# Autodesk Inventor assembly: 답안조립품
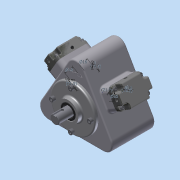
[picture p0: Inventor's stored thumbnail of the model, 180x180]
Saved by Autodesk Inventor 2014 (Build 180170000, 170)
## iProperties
Created: 2015-06
Part Number: 답안조립품
Document SubType Name: Assembly
Designer: MYHOME
Author: MYHOME
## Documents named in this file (20)
- C:\Documents and Settings\MYHOME\바탕 화면\350605V1037\답안조립품.iam
- C:\Documents and Settings\MYHOME\바탕 화면\350605V1037\본체.ipt
- C:\Documents and Settings\MYHOME\바탕 화면\350605V1037\헤더커버.ipt
- 헤더커버.ipt
- C:\Documents and Settings\MYHOME\바탕 화면\350605V1037\부시.ipt
- C:\Documents and Settings\MYHOME\바탕 화면\350605V1037\베어링 NA 4904.ipt
- 베어링 NA 4904.ipt
- C:\Documents and Settings\MYHOME\바탕 화면\350605V1037\편심축.ipt
- C:\Documents and Settings\MYHOME\바탕 화면\350605V1037\앞커버.ipt
- C:\Documents and Settings\MYHOME\바탕 화면\350605V1037\오일실.ipt
- 오일실.ipt
- C:\Documents and Settings\MYHOME\바탕 화면\350605V1037\M6x0.7x20.ipt
- M6x0.7x20.ipt
- C:\Documents and Settings\MYHOME\바탕 화면\350605V1037\슬라이드.ipt
- C:\Documents and Settings\MYHOME\바탕 화면\350605V1037\M4x0.5x16.ipt
- M4x0.5x16.ipt
- C:\Documents and Settings\MYHOME\바탕 화면\350605V1037\8-스프링.ipt
- C:\Documents and Settings\MYHOME\바탕 화면\350605V1037\9-스프링.ipt
- C:\Documents and Settings\MYHOME\바탕 화면\350605V1037\10-스프링.ipt
- C:\Documents and Settings\MYHOME\바탕 화면\350605V1037\11-스프링.ipt
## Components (18 placed, 7 different names)
1. 헤더커버:1
2. 헤더커버:2
3. M4x0.5x16:1
4. M4x0.5x16:2
5. M4x0.5x16:3
6. M4x0.5x16:4
7. M4x0.5x16:5
8. M4x0.5x16:6
9. M4x0.5x16:7
10. M4x0.5x16:8
11. 8-스프링:1
12. 9-스프링:1
13. 10-스프링:1
14. 11-스프링:1
15. M6x0.7x20:1
16. M6x0.7x20:2
17. M6x0.7x20:3
18. M6x0.7x20:4
